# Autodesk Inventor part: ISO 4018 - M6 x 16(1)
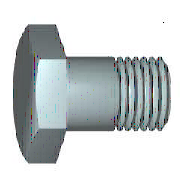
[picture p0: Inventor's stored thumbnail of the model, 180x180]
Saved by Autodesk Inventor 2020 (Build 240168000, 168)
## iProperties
Created: 2019-01
Part Number: ISO 4018 - M6 x 16(1)
Material: Ocel
Description: Šrouby se šestihrannou hlavou se závitem k hlavě. Výrobní třída C
Document SubType Name: Modeling
Standard: ISO 4018
Designer: doma
Standard Revision: Fourth edition 2011-04-01
Standards Organization: ISO
Language: cs-CZ
Size Designation: M6 x 16
Categories: <MemberInstance><Categories><Category DisplayName="Spojovací materiál" InternalName="e4da775c-781d-43d5-af7c-5136215cf5a6" Mnemonic="FSTN"><Category DisplayName
Density: 7.85 g/cm^3
Appearance: Plech
IsCustomPart: 0
Author: doma
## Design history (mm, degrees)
node "WorkPlane1"
node "WorkPoint1"
node "MSC_A1"
node "MSC_PF1"
node "MSC_PT1"
body "Solid1"
node "Náčrt1"
sketch "Náčrt2"
  geometry: L1 (-5, 2.887)-(-5, -2.887); L2 (0, 5.773)-(-5, 2.887); L3 (5, 2.887)-(0, 5.773); L4 (5, -2.887)-(5, 2.887); L5 (0, -5.773)-(5, -2.887); L6 (-5, -2.887)-(0, -5.773); C1 r 5 at (0, 0); 1 further point
  constraints: 12 end point, 6 tangent, 2 parallel, 2 vertical, 1 centre point
  dimensions: "d1" = 10 diameter of C1 (= ParS); "d29" = 0 distance of point (0, 0) C1.centre; "d30" = 0 distance of C1.centre point (0, 0)
extrude "Vysunutí1" new body sketch "Náčrt2" distance "d6" = 4 (= ParK); taper "d7" = 0 deg
revolve "Rotace1" stored, may be unused: angle "d14" = 360 deg
revolve "Rotace2" stored, may be unused: angle "d21" = 360 deg
chamfer "Zkosení1" distance "d22" = 0.5 (= 0.5 x PTC); stored, may be unused: second distance "d23" = 0.5 (= 0.5 x PTC), angle "d39" = 45 deg
fillet "Zaoblení1" dims "d24" = 0.25 (= r)
feature "Závit1" dims "d32" = 0, "b" = 14 (= NLG - 2 x PTC)
sketch "Náčrt3"
  geometry: L1 (5, 4)-(5.873, 4); L2 (5.873, 3.496)-(5, 4); L3 (5.873, 4)-(5.873, 3.496); L4 (0, -0.8)-(0, 4.8) reference; L5 (5.773, 0)-(5.773, 4) reference
  constraints: 6 end point, 1 horizontal, 1 vertical
  dimensions: "d25" = 0.1 distance between parallel lines of L5 L3; "d26" = 0 distance from line of L5.end L1; "d27" = 60 deg angle of L3 L2; "d28" = 5 distance from line of L4 L1.start (= 0.5 x ParS)
sketch "Náčrt4"
  geometry: L1 (0, -16)-(0, 0); L2 (-3, -16)-(0, -16); L3 (-3, 0)-(-3, -16); L4 (0, 0)-(-3, 0); L5 (0, -16)-(0, 0); L6 (-3.6, 0)-(0.6, 0) reference; L7 (0, -19.2)-(0, 3.2) reference
  constraints: 10 end point, 2 horizontal, 2 vertical
  dimensions: "d18" = 3 distance of L1.start L2.start (= 0.5 x NND); "d20" = 16 distance of L3.start L2.start (= NLG); "d33" = 0 distance between parallel lines of L7 L1; "d34" = 0 distance between parallel lines of L6 L4
other parameters: "NND" = 6 [user parameter; used in 2 equation terms], "NLG" = 16 [user parameter; used in 2 equation terms], "PTC" = 1 [user parameter; used in 3 equation terms], "ParK" = 4 [user parameter; used in 1 equation term], "ParS" = 10 [user parameter; used in 3 equation terms], "msp_es" = 5.77367 (= 0.577367 x ParS) [user parameter], "r" = 0.25 [user parameter; used in 1 equation term], "d2" = 15 (derived), "d4" = 17.32102 (derived), "d8" = 15 (derived), "d10" = 0 (derived), "d12" = 30 deg (derived), "d15" = 0 (derived), "d37" = 0, "d38" = 0, "d40" = 0, "d41" = 0, "d42" = 0, "THREADDIA" = 6 (= NND) [user parameter]
